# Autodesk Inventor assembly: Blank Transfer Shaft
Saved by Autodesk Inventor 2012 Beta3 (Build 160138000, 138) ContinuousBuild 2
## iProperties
Created: 2011-01
Part Number: Blank Transfer Shaft
Document SubType Name: Assembly
Designer: Beta-8540w
ClientObjectVersion: 1
Author: Beta-8540w
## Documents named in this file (2)
- C:\Inventor 2012 Essentials\Assemblies\Chapter 8\Design Accelerators\Blank Transfer Shaft.iam
- C:\Inventor 2012 Essentials\Assemblies\Chapter 8\Design Accelerators\Blank Transfer Shaft.ipt
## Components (1 placed, 1 different names)
1. Blank Transfer Shaft:1
